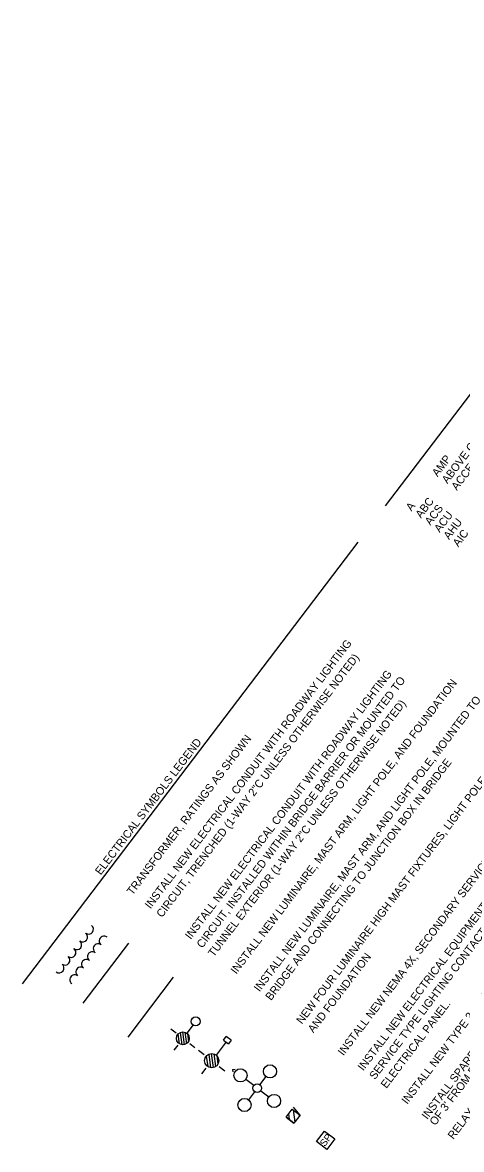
# Model space of a CAD drawing. Extents: x 1289840 to 1300655, y 220865 to 232830.
# Drawn here: x 1298552 to 1298895, y 231152 to 232032 of the extents above; entities that cross this region are included whole.
import ezdxf

# ---------------------------------------------------------------- set-up
doc = ezdxf.new("R2010")
doc.units = 0
for name, color, linetype in [('B-Gen-Annotation', 7, 'Continuous'), ('E-ANNO-NOTE', 7, 'Continuous'), ('E-ANNO-SYMB', 7, 'Continuous'), ('E-DETL-EQPM-PCKG', 7, 'Continuous'), ('E-LITE-CIRC', 7, 'Continuous'), ('E-LITE-EXTR', 7, 'Continuous'), ('E-LITE-EXTR-NEW', 7, 'Continuous'), ('E-POWR-IDEN', 7, 'Continuous'), ('E-POWR-JBOX', 7, 'Continuous'), ('ILLUMINATION_LEGEND', 7, 'Continuous')]:
    doc.layers.add(name, color=color, linetype=linetype)

# ---------------------------------------------------------------- blocks, each defined once
blk = doc.blocks.new('MAINXFMR-flat-1')
at = {"layer": 'E-ANNO-SYMB'}
for centre, start, end in [((-3.26, 1.3), 180, 0), ((-1.95, 1.3), 180, 360), ((-0.65, 1.3), 180, 360), ((0.65, 1.3), 180, 0), ((1.95, 1.3), 180, 0), ((3.26, 1.3), 180, 0), ((-3.26, -1.3), 0, 180), ((-1.95, -1.3), 0, 180), ((-0.65, -1.3), 0, 180), ((0.65, -1.3), 360, 180), ((1.95, -1.3), 360, 180), ((3.26, -1.3), 0, 180)]:
    blk.add_arc(centre, 0.651, start, end, dxfattribs=at)

msp = doc.modelspace()

# ---------------------------------------------------------------- linework, layer by layer
at = {"layer": 'E-ANNO-NOTE'}
for p, q in [((1298835.62, 231654.68), (1299122.78, 232032.31)), ((1298551.8, 231281.43), (1298814.19, 231626.5))]:
    msp.add_line(p, q, dxfattribs=at)
at = {"layer": 'E-LITE-CIRC'}
for p, q in [((1298599.26, 231266.4), (1298634.87, 231313.23)), ((1298634.27, 231239.78), (1298669.88, 231286.61))]:
    msp.add_line(p, q, dxfattribs=at)
at = {"layer": 'E-LITE-EXTR'}
msp.add_line((1298757.81, 231177.4), (1298764.03, 231172.67), dxfattribs=at)
at = {"layer": 'E-LITE-EXTR-NEW'}
for p, q in [((1298685.09, 231249.27), (1298680.18, 231242.81)), ((1298671.81, 231242.86), (1298667.81, 231245.9)), ((1298673.33, 231242.09), (1298674.35, 231234.63)), ((1298675.01, 231243.36), (1298676.3, 231233.85)), ((1298676.8, 231243.82), (1298678.15, 231233.89)), ((1298678.68, 231243.59), (1298679.9, 231234.61)), ((1298680.69, 231242.36), (1298681.51, 231236.33)), ((1298709.03, 231237.49), (1298711.09, 231240.21)), ((1298709.03, 231237.49), (1298712.72, 231234.68)), ((1298714.79, 231237.4), (1298711.09, 231240.21)), ((1298714.79, 231237.4), (1298712.72, 231234.68)), ((1298673.09, 231233.48), (1298670.05, 231229.48)), ((1298682.47, 231234.75), (1298686.47, 231231.71)), ((1298693.8, 231225.89), (1298689.37, 231229.26)), ((1298710.88, 231236.09), (1298703.08, 231225.83)), ((1298695.49, 231225.03), (1298696.61, 231216.77)), ((1298697.35, 231226.44), (1298698.78, 231215.91)), ((1298699.33, 231226.95), (1298700.82, 231215.95)), ((1298701.41, 231226.7), (1298702.76, 231216.75)), ((1298703.64, 231225.34), (1298704.55, 231218.66)), ((1298695.21, 231215.49), (1298691.84, 231211.06)), ((1298705.62, 231216.91), (1298710.05, 231213.54)), ((1298716.01, 231214.57), (1298718.03, 231214.82)), ((1298716.01, 231214.57), (1298716.31, 231212.57)), ((1298732.56, 231201.99), (1298726.25, 231206.79)), ((1298737.36, 231202.65), (1298742.17, 231208.96)), ((1298733.22, 231197.19), (1298728.41, 231190.87)), ((1298738.02, 231197.84), (1298744.33, 231193.04))]:
    msp.add_line(p, q, dxfattribs=at)
for centre, radius in [((1298687.22, 231252.06), 3.51), ((1298677.14, 231238.81), 5.02), ((1298699.71, 231221.4), 5.57), ((1298722.15, 231209.91), 5.14), ((1298745.28, 231213.05), 5.14), ((1298735.29, 231199.92), 3.43), ((1298748.43, 231189.93), 5.14), ((1298725.3, 231186.78), 5.14)]:
    msp.add_circle(centre, radius, dxfattribs=at)
at = {"layer": 'E-POWR-JBOX'}
for p, q in [((1298781.58, 231158.26), (1298787.8, 231166.44)), ((1298789.76, 231152.05), (1298781.58, 231158.26)), ((1298787.8, 231166.44), (1298795.98, 231160.22)), ((1298795.98, 231160.22), (1298789.76, 231152.05))]:
    msp.add_line(p, q, dxfattribs=at)
at = {"layer": 'ILLUMINATION_LEGEND'}
for p, q in [((1298768.75, 231178.89), (1298763.72, 231185.17)), ((1298759.77, 231179.98), (1298760.38, 231175.44)), ((1298763.29, 231183.05), (1298764.6, 231173.43)), ((1298767.69, 231179.7), (1298767.94, 231177.82))]:
    msp.add_line(p, q, dxfattribs=at)
msp.add_lwpolyline([(1298764.03, 231172.67), (1298757.81, 231177.4), (1298762.54, 231183.62), (1298768.75, 231178.89), (1298764.03, 231172.67)], dxfattribs=at)

# ---------------------------------------------------------------- block references
at = {"layer": 'E-DETL-EQPM-PCKG', "xscale": 5.833333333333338, "yscale": 5.833333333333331, "rotation": 52.750131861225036}
msp.add_blockref('MAINXFMR-flat-1', (1298598, 231304.31), dxfattribs=at)

# ---------------------------------------------------------------- texts
at = {"layer": 'B-Gen-Annotation'}
msp.add_text('ELECTRICAL SYMBOLS LEGEND', height=6.25, rotation=52.75013, dxfattribs=at).set_placement((1298612.94, 231365.97))
at = {"layer": 'E-ANNO-NOTE'}
for s, rotation, p in [('ACCESS CONTROL SYSTEM', 52.75013, (1298891.4, 231666.41)), ('ABOVE COUNTER', 52.75013, (1298883.98, 231671.68)), ('AMP', 52.75013, (1298876.27, 231677.08)), ('ABC', 52.75013, (1298863.33, 231644.68)), ('A', 52.75013, (1298855.86, 231650.24)), ('ACS', 52.75013, (1298870.66, 231639.14)), ('ACU', 52.75013, (1298877.95, 231633.54)), ('AHU', 52.75013, (1298885.27, 231627.97)), ('AIC', 52.75013, (1298892.5, 231622.26)), ('INSTALL NEW ELECTRICAL CONDUIT WITH ROADWAY LIGHTING ', 52.79521, (1298651.83, 231339.55)), ('CIRCUIT, TRENCHED (1-WAY 2"C UNLESS OTHERWISE NOTED)', 52.79521, (1298660.85, 231332.71)), ('INSTALL NEW ELECTRICAL CONDUIT WITH ROADWAY LIGHTING ', 52.79521, (1298683.27, 231315.65)), ('CIRCUIT, INSTALLED WITHIN BRIDGE BARRIER OR MOUNTED TO ', 52.79521, (1298692.29, 231308.8)), ('INSTALL NEW LUMINAIRE, MAST ARM, LIGHT POLE, AND FOUNDATION', 52.79521, (1298718.9, 231288.56)), ('TUNNEL EXTERIOR (1-WAY 2"C UNLESS OTHERWISE NOTED)', 52.79521, (1298701.3, 231301.96)), ('INSTALL NEW LUMINAIRE, MAST ARM, AND LIGHT POLE, MOUNTED TO ', 52.79521, (1298737.07, 231274.72)), ('TRANSFORMER, RATINGS AS SHOWN', 52.75013, (1298637.77, 231350.24)), ('BRIDGE AND CONNECTING TO JUNCTION BOX IN BRIDGE', 52.79521, (1298746.09, 231267.88)), ('NEW FOUR LUMINAIRE HIGH MAST FIXTURES, LIGHT POLE, ', 52.79521, (1298770.24, 231249.49)), ('INSTALL NEW ELECTRICAL EQUIPMENT PEDESTAL, INCLUDING PEC, ', 52.79521, (1298818.24, 231212.98)), ('INSTALL NEW NEMA 4X, SECONDARY SERVICE PEDESTAL.', 52.79521, (1298802.69, 231224.81)), ('SERVICE TYPE LIGHTING CONTACTOR, UTILITY METER, AND ', 52.79521, (1298827.26, 231206.13)), ('INSTALL SPARE 2" CONDUIT STUB-OUT TO A MINIMUM ', 52.75013, (1298868.2, 231175.02)), ('AND FOUNDATION', 52.79521, (1298779.26, 231242.64)), ('INSTALL NEW TYPE 2 HD PULL BOX', 52.75013, (1298852.54, 231186.92)), ('RELAY CONTACT, NORMALLY OPEN.', 52.79521, (1298888.63, 231159.48)), ('ELECTRICAL PANEL.', 52.79521, (1298836.28, 231199.29)), ("OF 3' FROM PULLBOX EDGE", 52.75013, (1298874.42, 231170.28))]:
    msp.add_text(s, height=6.25, rotation=rotation, dxfattribs=at).set_placement(p)
at = {"layer": 'E-POWR-IDEN'}
msp.add_text('SP', height=5.5, rotation=52.75013, dxfattribs=at).set_placement((1298788.14, 231153.85))

doc.saveas('drawing.dxf')
